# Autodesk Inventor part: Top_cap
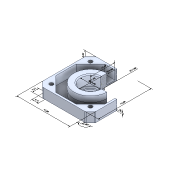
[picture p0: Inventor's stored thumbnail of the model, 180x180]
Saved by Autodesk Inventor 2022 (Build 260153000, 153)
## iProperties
Created: 2020-10
Part Number: Top_cap
Material: Generico
Document SubType Name: Modeling
Designer: admin
Density: 1 g/cm^3
Appearance: Default
Sending System: SolidWorks 2020
Last Author: Simon
Last Saved: 2020-10-31
Author: admin
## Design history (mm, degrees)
node "Annotazioni"
  node "Quota lineare 1" dims "d2" = 42 (derived), "d39" = 15, "d40" = 0
  node "Quota lineare 2" dims "d5" = 42 (derived), "d39" = 15, "d40" = 0
  node "Quota lineare 3" dims "d7" = 8 (derived), "d39" = 15, "d40" = 0
  node "Quota diametro 1" dims "d9" = 9 (derived), "d39" = 15, "d40" = 0
  node "Quota diametro 2" dims "d11" = 10 (derived), "d39" = 15, "d40" = 0
  node "Quota diametro 3" dims "d13" = 21.5 (derived), "d39" = 15, "d40" = 0
  node "Quota angolare 1" dims "d16" = 135 deg (derived), "d39" = 15, "d40" = 0
  node "Quota diametro 4" dims "d18" = 12 (derived), "d39" = 15, "d40" = 0
  node "Quota diametro 5" dims "d20" = 16 (derived), "d39" = 15, "d40" = 0
  node "Quota diametro 6" dims "d22" = 17.5 (derived), "d39" = 15, "d40" = 0
  node "Quota radiale 1" dims "d24" = 13 (derived), "d39" = 15, "d40" = 0
  node "Quota lineare 4" dims "d26" = 5.11469 (derived), "d39" = 15, "d40" = 0
  node "Quota lineare 5" dims "d28" = 5.11469 (derived), "d39" = 15, "d40" = 0
  node "Quota lineare 6" dims "d31" = 2 (derived), "d39" = 15, "d40" = 0
  node "Quota lineare 7" dims "d32" = 1 (derived), "d39" = 15, "d40" = 0
  node "Quota lineare 8" dims "d34" = 19.5 (derived), "d39" = 15, "d40" = 0
  node "Quota diametro 7" dims "d36" = 3 (derived), "d39" = 15, "d40" = 0
fillet "Fillet4"
feature "Filettatura1" dims "d37" = 15, "d38" = 0
feature "Filettatura2" dims "d39" = 15, "d40" = 0
feature "Filettatura3" dims "d41" = 15, "d42" = 0
node "Solido1"
other parameters: "d0" = 6.93847 (derived), "d1" = 7.89627 (derived), "d10" = 43.20813 (derived), "d12" = 45.7061 (derived), "d14" = 5.0818 (derived), "d15" = 0.84157 (derived), "d17" = 31.33322 (derived), "d19" = 15.82524 (derived), "d21" = 31.18508 (derived), "d23" = 30.91965 (derived), "d25" = 9.51676 (derived), "d27" = 0.91927 (derived), "d29" = 7.68128 (derived), "d3" = 9.31564 (derived), "d30" = 2.29443 (derived), "d33" = -3.39083 (derived), "d35" = 37.22751 (derived), "d4" = 2.17137 (derived), "d6" = 5.37399 (derived), "d8" = 3.13288 (derived)
